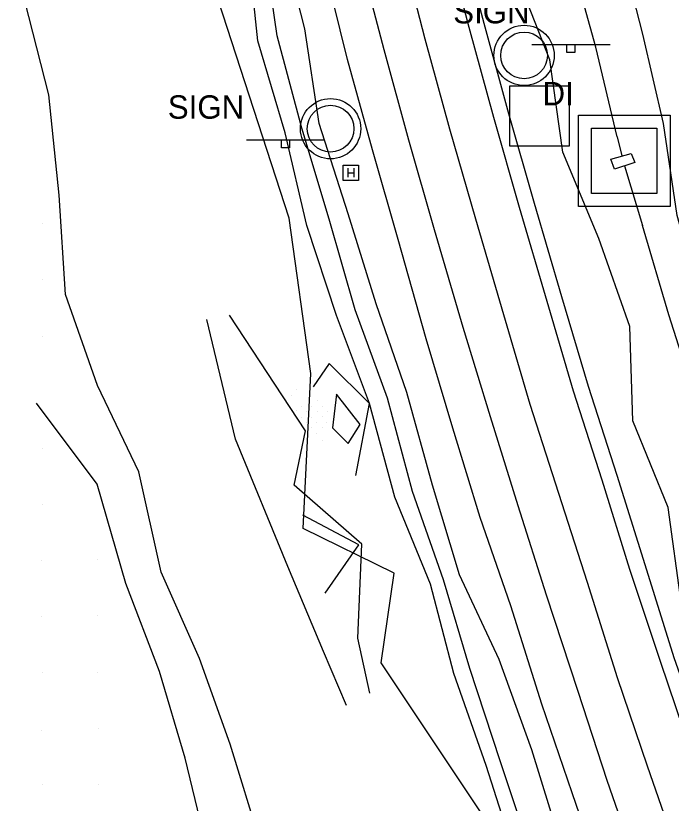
# Model space of a CAD drawing. Extents: x 1602514 to 1609837, y 863887 to 871157.
# Drawn here: x 1604320.5 to 1604495.8, y 868706.1 to 868916.6 of the extents above; entities that cross this region are included whole.
import ezdxf

# ---------------------------------------------------------------- set-up
doc = ezdxf.new("R2010")
doc.units = 0
for name, color, linetype in [('Drainage-Structures', 7, 'Continuous'), ('Lighting_Signals-Equipment', 7, 'Continuous'), ('Roadway-Signs', 7, 'Continuous'), ('Survey-Centerline', 7, 'Continuous'), ('Survey-Drainage structures-concrete', 7, 'Continuous'), ('Survey-Edge of pavement', 7, 'Continuous'), ('Survey-Flow line', 7, 'Continuous'), ('Survey-Ridge Lines', 7, 'Continuous'), ('Survey-Shoulders', 7, 'Continuous'), ('Survey-Signals', 7, 'Continuous'), ('Survey-Spot dirt', 7, 'Continuous'), ('Survey-Spot rock', 7, 'Continuous'), ('Survey-Vegetation trees', 7, 'Continuous'), ('USER-Handhole', 7, 'Continuous')]:
    doc.layers.add(name, color=color, linetype=linetype)

msp = doc.modelspace()

# ---------------------------------------------------------------- linework, layer by layer
at = {"layer": 'Drainage-Structures'}
for p, q in [((1604470.99, 868890.09), (1604495.49, 868890.09)), ((1604470.99, 868865.59), (1604470.99, 868890.09)), ((1604470.99, 868890.09), (1604495.49, 868890.09)), ((1604470.99, 868865.59), (1604470.99, 868890.09)), ((1604495.49, 868890.09), (1604495.49, 868865.59)), ((1604495.49, 868890.09), (1604495.49, 868865.59)), ((1604474.49, 868886.59), (1604491.99, 868886.59)), ((1604474.49, 868869.09), (1604474.49, 868886.59)), ((1604474.49, 868886.59), (1604491.99, 868886.59)), ((1604474.49, 868869.09), (1604474.49, 868886.59)), ((1604491.99, 868886.59), (1604491.99, 868869.09)), ((1604491.99, 868886.59), (1604491.99, 868869.09)), ((1604491.99, 868869.09), (1604474.49, 868869.09)), ((1604491.99, 868869.09), (1604474.49, 868869.09)), ((1604495.49, 868865.59), (1604470.99, 868865.59)), ((1604495.49, 868865.59), (1604470.99, 868865.59))]:
    msp.add_line(p, q, dxfattribs=at)
at = {"layer": 'Lighting_Signals-Equipment'}
msp.add_lwpolyline([(1604452.56, 868881.84), (1604468.56, 868881.84), (1604468.56, 868897.84), (1604452.56, 868897.84)], close=True, dxfattribs=at)
msp.add_lwpolyline([(1604452.56, 868881.84), (1604468.56, 868881.84), (1604468.56, 868897.84), (1604452.56, 868897.84)], close=True, dxfattribs=at)
at = {"layer": 'Roadway-Signs'}
for p, q in [((1604458.57, 868908.94), (1604479.47, 868908.94)), ((1604458.57, 868908.94), (1604479.47, 868908.94)), ((1604467.92, 868906.84), (1604467.92, 868908.94)), ((1604467.92, 868906.84), (1604467.92, 868908.94)), ((1604468.97, 868908.94), (1604468.97, 868908.94)), ((1604468.97, 868908.94), (1604468.97, 868908.94)), ((1604470.02, 868908.94), (1604470.02, 868906.84)), ((1604470.02, 868908.94), (1604470.02, 868906.84)), ((1604470.02, 868906.84), (1604467.92, 868906.84)), ((1604470.02, 868906.84), (1604467.92, 868906.84)), ((1604382.22, 868883.46), (1604403.12, 868883.46)), ((1604382.22, 868883.46), (1604403.12, 868883.46)), ((1604391.57, 868881.36), (1604391.57, 868883.46)), ((1604391.57, 868881.36), (1604391.57, 868883.46)), ((1604392.62, 868883.46), (1604392.62, 868883.46)), ((1604392.62, 868883.46), (1604392.62, 868883.46)), ((1604393.67, 868883.46), (1604393.67, 868881.36)), ((1604393.67, 868883.46), (1604393.67, 868881.36)), ((1604393.67, 868881.36), (1604391.57, 868881.36)), ((1604393.67, 868881.36), (1604391.57, 868881.36))]:
    msp.add_line(p, q, dxfattribs=at)
at = {"layer": 'Survey-Centerline'}
msp.add_lwpolyline([(1604581.44, 868481.09), (1604571.34, 868503.97), (1604561.56, 868526.97), (1604551.97, 868550.06), (1604542.71, 868573.28), (1604533.56, 868596.55), (1604523.63, 868621.98), (1604514.83, 868645.38), (1604506.1, 868668.81), (1604497.66, 868692.34), (1604489.5, 868715.97), (1604481.4, 868739.62), (1604473.39, 868765.08), (1604465.73, 868788.88), (1604458.1, 868812.69), (1604451, 868836.66), (1604443.51, 868862.25), (1604436.63, 868886.29), (1604429.99, 868910.39), (1604423.73, 868934.59)], dxfattribs=at)
msp.add_lwpolyline([(1604581.44, 868481.09), (1604571.34, 868503.97), (1604561.56, 868526.97), (1604551.97, 868550.06), (1604542.71, 868573.28), (1604533.56, 868596.55), (1604523.63, 868621.98), (1604514.83, 868645.38), (1604506.1, 868668.81), (1604497.66, 868692.34), (1604489.5, 868715.97), (1604481.4, 868739.62), (1604473.39, 868765.08), (1604465.73, 868788.88), (1604458.1, 868812.69), (1604451, 868836.66), (1604443.51, 868862.25), (1604436.63, 868886.29), (1604429.99, 868910.39), (1604423.73, 868934.59)], dxfattribs=at)
at = {"layer": 'Survey-Drainage structures-concrete'}
msp.add_lwpolyline([(1604479.68, 868878.3), (1604485.13, 868879.84), (1604486.1, 868877.4), (1604480.62, 868875.64)], close=True, dxfattribs=at)
msp.add_lwpolyline([(1604479.68, 868878.3), (1604485.13, 868879.84), (1604486.1, 868877.4), (1604480.62, 868875.64)], close=True, dxfattribs=at)
at = {"layer": 'Survey-Edge of pavement'}
for points in [[(1604592.91, 868485.86), (1604582.8, 868508.73), (1604573.03, 868531.74), (1604563.26, 868554.75), (1604554, 868577.97), (1604544.85, 868601.23), (1604535.01, 868625.97), (1604526.24, 868649.39), (1604517.66, 868672.87), (1604509.23, 868696.4), (1604501.06, 868720.03), (1604493.04, 868743.71), (1604484.74, 868768.56), (1604477.34, 868792.44), (1604469.71, 868816.25), (1604462.61, 868840.22), (1604455.25, 868865.35), (1604448.37, 868889.39), (1604441.73, 868913.49), (1604435.47, 868937.69)], [(1604592.91, 868485.86), (1604582.8, 868508.73), (1604573.03, 868531.74), (1604563.26, 868554.75), (1604554, 868577.97), (1604544.85, 868601.23), (1604535.01, 868625.97), (1604526.24, 868649.39), (1604517.66, 868672.87), (1604509.23, 868696.4), (1604501.06, 868720.03), (1604493.04, 868743.71), (1604484.74, 868768.56), (1604477.34, 868792.44), (1604469.71, 868816.25), (1604462.61, 868840.22), (1604455.25, 868865.35), (1604448.37, 868889.39), (1604441.73, 868913.49), (1604435.47, 868937.69)], [(1604570.96, 868476.74), (1604560.86, 868499.61), (1604551.08, 868522.62), (1604541.49, 868545.7), (1604532.23, 868568.93), (1604523.08, 868592.19), (1604512.78, 868618.17), (1604503.9, 868641.54), (1604495.32, 868665.02), (1604486.88, 868688.56), (1604478.71, 868712.18), (1604470.88, 868735.92), (1604462.47, 868761.74), (1604454.88, 868785.56), (1604447.48, 868809.43), (1604440.12, 868833.32), (1604432.5, 868859.35), (1604425.62, 868883.39), (1604418.98, 868907.49), (1604412.72, 868931.69)], [(1604570.96, 868476.74), (1604560.86, 868499.61), (1604551.08, 868522.62), (1604541.49, 868545.7), (1604532.23, 868568.93), (1604523.08, 868592.19), (1604512.78, 868618.17), (1604503.9, 868641.54), (1604495.32, 868665.02), (1604486.88, 868688.56), (1604478.71, 868712.18), (1604470.88, 868735.92), (1604462.47, 868761.74), (1604454.88, 868785.56), (1604447.48, 868809.43), (1604440.12, 868833.32), (1604432.5, 868859.35), (1604425.62, 868883.39), (1604418.98, 868907.49), (1604412.72, 868931.69)]]:
    msp.add_lwpolyline(points, dxfattribs=at)
at = {"layer": 'Survey-Flow line'}
for p, q in [((1604481.36, 868884.29), (1604482.63, 868879.14)), ((1604481.36, 868884.29), (1604482.63, 868879.14)), ((1604483.35, 868876.51), (1604488.15, 868860.51)), ((1604483.35, 868876.51), (1604488.15, 868860.51))]:
    msp.add_line(p, q, dxfattribs=at)
for points in [[(1604481.36, 868884.29), (1604475.64, 868908.22), (1604469.14, 868931.65), (1604463.08, 868955.47), (1604458.26, 868979.46), (1604449.71, 869003.69), (1604443.08, 869026.72), (1604439.12, 869050.16), (1604431.9, 869074.97), (1604426.97, 869098.97), (1604423.02, 869123.51), (1604419.66, 869147.75), (1604413.92, 869171.75), (1604412.56, 869196.69), (1604406.79, 869220.46), (1604403.76, 869245.16), (1604400.6, 869269.02), (1604399.12, 869279.06)], [(1604481.36, 868884.29), (1604475.64, 868908.22), (1604469.14, 868931.65), (1604463.08, 868955.47), (1604458.26, 868979.46), (1604449.71, 869003.69), (1604443.08, 869026.72), (1604439.12, 869050.16), (1604431.9, 869074.97), (1604426.97, 869098.97), (1604423.02, 869123.51), (1604419.66, 869147.75), (1604413.92, 869171.75), (1604412.56, 869196.69), (1604406.79, 869220.46), (1604403.76, 869245.16), (1604400.6, 869269.02), (1604399.12, 869279.06)], [(1604537.67, 868479.78), (1604531.49, 868504.94), (1604521.95, 868528.36), (1604512.39, 868552.01), (1604502.89, 868575.32), (1604493.37, 868598.54), (1604484.21, 868622.28), (1604474.86, 868645.6), (1604466.13, 868669.53), (1604457.95, 868693.59), (1604450.01, 868717.41), (1604441.97, 868742.06), (1604434.89, 868765.77), (1604426.64, 868789.43), (1604419.87, 868814.36), (1604411.3, 868838), (1604404.27, 868862.24), (1604397, 868886.54), (1604390.36, 868911.27), (1604386.73, 868936.5)], [(1604537.67, 868479.78), (1604531.49, 868504.94), (1604521.95, 868528.36), (1604512.39, 868552.01), (1604502.89, 868575.32), (1604493.37, 868598.54), (1604484.21, 868622.28), (1604474.86, 868645.6), (1604466.13, 868669.53), (1604457.95, 868693.59), (1604450.01, 868717.41), (1604441.97, 868742.06), (1604434.89, 868765.77), (1604426.64, 868789.43), (1604419.87, 868814.36), (1604411.3, 868838), (1604404.27, 868862.24), (1604397, 868886.54), (1604390.36, 868911.27), (1604386.73, 868936.5)], [(1604631.16, 868467.42), (1604624.49, 868491.01), (1604614.43, 868513.69), (1604605.42, 868536.34), (1604595.9, 868559.08), (1604587.3, 868581.88), (1604579.51, 868605.45), (1604568.58, 868627.9), (1604559.84, 868650.74), (1604547.23, 868672.57), (1604538.84, 868695.58), (1604533.62, 868719.75), (1604526.86, 868743.71), (1604517.89, 868765.93), (1604508.44, 868789.46), (1604502.45, 868813.72), (1604495.18, 868836.65), (1604488.15, 868860.51)], [(1604631.16, 868467.42), (1604624.49, 868491.01), (1604614.43, 868513.69), (1604605.42, 868536.34), (1604595.9, 868559.08), (1604587.3, 868581.88), (1604579.51, 868605.45), (1604568.58, 868627.9), (1604559.84, 868650.74), (1604547.23, 868672.57), (1604538.84, 868695.58), (1604533.62, 868719.75), (1604526.86, 868743.71), (1604517.89, 868765.93), (1604508.44, 868789.46), (1604502.45, 868813.72), (1604495.18, 868836.65), (1604488.15, 868860.51)]]:
    msp.add_lwpolyline(points, dxfattribs=at)
at = {"layer": 'Survey-Ridge Lines'}
msp.add_line((1604415.19, 868735.5), (1604412.02, 868750.19), dxfattribs=at)
msp.add_line((1604415.19, 868735.5), (1604412.02, 868750.19), dxfattribs=at)
for points in [[(1604484.44, 868512.77), (1604471.23, 868535.6), (1604456.61, 868557.12), (1604443.28, 868578.98), (1604434.63, 868603.63), (1604419.68, 868625.03), (1604407.62, 868648.56), (1604398.97, 868673.19), (1604385.98, 868695.5), (1604377.79, 868721.88), (1604369.61, 868744.74), (1604359.38, 868767.89), (1604353.35, 868794.66), (1604342.37, 868817.81), (1604333.79, 868842.09), (1604332.04, 868868.63), (1604329.31, 868895.47), (1604322.89, 868920.63), (1604325.28, 868948.19), (1604325.84, 868972.83), (1604330.44, 869001.73), (1604324.91, 869028.41), (1604328.01, 869053.17), (1604333.56, 869080.61)], [(1604484.44, 868512.77), (1604471.23, 868535.6), (1604456.61, 868557.12), (1604443.28, 868578.98), (1604434.63, 868603.63), (1604419.68, 868625.03), (1604407.62, 868648.56), (1604398.97, 868673.19), (1604385.98, 868695.5), (1604377.79, 868721.88), (1604369.61, 868744.74), (1604359.38, 868767.89), (1604353.35, 868794.66), (1604342.37, 868817.81), (1604333.79, 868842.09), (1604332.04, 868868.63), (1604329.31, 868895.47), (1604322.89, 868920.63), (1604325.28, 868948.19), (1604325.84, 868972.83), (1604330.44, 869001.73), (1604324.91, 869028.41), (1604328.01, 869053.17), (1604333.56, 869080.61)], [(1604525.88, 868529.99), (1604516.28, 868553.56), (1604507.05, 868576.96), (1604497.7, 868600.23), (1604489.01, 868624.08), (1604479.42, 868647.29), (1604473.39, 868672.13), (1604465.92, 868696.34), (1604458.57, 868720.34), (1604449.79, 868744.52), (1604439.2, 868767.16), (1604431.98, 868791.15), (1604425.09, 868815.9), (1604416.9, 868839.64), (1604409.38, 868863.7), (1604401.6, 868887.81), (1604397.76, 868913.18), (1604391.53, 868937.69)], [(1604525.88, 868529.99), (1604516.28, 868553.56), (1604507.05, 868576.96), (1604497.7, 868600.23), (1604489.01, 868624.08), (1604479.42, 868647.29), (1604473.39, 868672.13), (1604465.92, 868696.34), (1604458.57, 868720.34), (1604449.79, 868744.52), (1604439.2, 868767.16), (1604431.98, 868791.15), (1604425.09, 868815.9), (1604416.9, 868839.64), (1604409.38, 868863.7), (1604401.6, 868887.81), (1604397.76, 868913.18), (1604391.53, 868937.69)], [(1604517.46, 868526.49), (1604508.17, 868550.33), (1604497.85, 868573.34), (1604488.7, 868596.71), (1604479.59, 868620.54), (1604470.72, 868644.05), (1604462.42, 868668.2), (1604453.99, 868692.22), (1604446.34, 868716.16), (1604437.68, 868740.71), (1604431.41, 868764.65), (1604421.86, 868787.91), (1604415.12, 868812.95), (1604406.23, 868836.52), (1604398.33, 868860.54), (1604392.52, 868885.3), (1604385.23, 868909.94), (1604382.59, 868935.47)], [(1604517.46, 868526.49), (1604508.17, 868550.33), (1604497.85, 868573.34), (1604488.7, 868596.71), (1604479.59, 868620.54), (1604470.72, 868644.05), (1604462.42, 868668.2), (1604453.99, 868692.22), (1604446.34, 868716.16), (1604437.68, 868740.71), (1604431.41, 868764.65), (1604421.86, 868787.91), (1604415.12, 868812.95), (1604406.23, 868836.52), (1604398.33, 868860.54), (1604392.52, 868885.3), (1604385.23, 868909.94), (1604382.59, 868935.47)], [(1604601.1, 868561.24), (1604594.72, 868584.84), (1604587.27, 868608.51), (1604577.93, 868631.55), (1604568.41, 868653.96), (1604557.83, 868676.52), (1604551.51, 868700.12), (1604544.09, 868723.37), (1604537.6, 868747.39), (1604529.3, 868769.52), (1604521.74, 868793.75), (1604514.12, 868817.46), (1604504.05, 868839.28), (1604497.45, 868863.24), (1604493.73, 868887.83), (1604488.19, 868911.68), (1604482.21, 868935.03)], [(1604601.1, 868561.24), (1604594.72, 868584.84), (1604587.27, 868608.51), (1604577.93, 868631.55), (1604568.41, 868653.96), (1604557.83, 868676.52), (1604551.51, 868700.12), (1604544.09, 868723.37), (1604537.6, 868747.39), (1604529.3, 868769.52), (1604521.74, 868793.75), (1604514.12, 868817.46), (1604504.05, 868839.28), (1604497.45, 868863.24), (1604493.73, 868887.83), (1604488.19, 868911.68), (1604482.21, 868935.03)], [(1604580.26, 868552.59), (1604568.53, 868574.4), (1604563.05, 868598.98), (1604553.96, 868622.19), (1604545.16, 868645.21), (1604532.68, 868667.14), (1604527.97, 868691.68), (1604520.41, 868715.18), (1604510.05, 868737.96), (1604498.44, 868759.81), (1604495.03, 868785.14), (1604485.51, 868808.3), (1604484.73, 868833.56), (1604476.48, 868857.09), (1604466.79, 868880.12), (1604463.34, 868904.83), (1604454.33, 868927.82)], [(1604580.26, 868552.59), (1604568.53, 868574.4), (1604563.05, 868598.98), (1604553.96, 868622.19), (1604545.16, 868645.21), (1604532.68, 868667.14), (1604527.97, 868691.68), (1604520.41, 868715.18), (1604510.05, 868737.96), (1604498.44, 868759.81), (1604495.03, 868785.14), (1604485.51, 868808.3), (1604484.73, 868833.56), (1604476.48, 868857.09), (1604466.79, 868880.12), (1604463.34, 868904.83), (1604454.33, 868927.82)], [(1604394.96, 868791.16), (1604397.98, 868805.61), (1604377.6, 868836.58)], [(1604394.96, 868791.16), (1604397.98, 868805.61), (1604377.6, 868836.58)], [(1604408.97, 868732.19), (1604402.75, 868746.65), (1604393.28, 868769.36), (1604379.22, 868803.41), (1604371.59, 868835.41)], [(1604408.97, 868732.19), (1604402.75, 868746.65), (1604393.28, 868769.36), (1604379.22, 868803.41), (1604371.59, 868835.41)], [(1604411.43, 868793.68), (1604415.12, 868812.95), (1604404.35, 868823.61), (1604400.01, 868817.42)], [(1604411.43, 868793.68), (1604415.12, 868812.95), (1604404.35, 868823.61), (1604400.01, 868817.42)], [(1604473.45, 868508.21), (1604462.16, 868531.98), (1604447.84, 868553.67), (1604427.45, 868572.81), (1604422.01, 868598.88), (1604406.2, 868620.01), (1604394.65, 868643.92), (1604390.97, 868670.42), (1604372.39, 868690.85), (1604365.74, 868718.09), (1604358.94, 868741.3), (1604349.92, 868764.86), (1604342.27, 868791.38), (1604325.98, 868813.02)], [(1604473.45, 868508.21), (1604462.16, 868531.98), (1604447.84, 868553.67), (1604427.45, 868572.81), (1604422.01, 868598.88), (1604406.2, 868620.01), (1604394.65, 868643.92), (1604390.97, 868670.42), (1604372.39, 868690.85), (1604365.74, 868718.09), (1604358.94, 868741.3), (1604349.92, 868764.86), (1604342.27, 868791.38), (1604325.98, 868813.02)], [(1604412.02, 868750.19), (1604413.02, 868775.37), (1604394.96, 868791.16)], [(1604412.02, 868750.19), (1604413.02, 868775.37), (1604394.96, 868791.16)]]:
    msp.add_lwpolyline(points, dxfattribs=at)
at = {"layer": 'Survey-Shoulders'}
for points in [[(1604596.75, 868487.46), (1604586.65, 868510.33), (1604576.88, 868533.34), (1604567.29, 868556.42), (1604558.03, 868579.64), (1604548.88, 868602.91), (1604539.13, 868627.42), (1604530.59, 868650.91), (1604521.52, 868674.22), (1604513.09, 868697.76), (1604504.92, 868721.38), (1604496.64, 868744.97), (1604488.83, 868769.81), (1604481.32, 868793.66), (1604473.69, 868817.47), (1604466.59, 868841.44), (1604459.27, 868866.41), (1604452.4, 868890.45), (1604445.75, 868914.55), (1604439.34, 868938.71)], [(1604596.75, 868487.46), (1604586.65, 868510.33), (1604576.88, 868533.34), (1604567.29, 868556.42), (1604558.03, 868579.64), (1604548.88, 868602.91), (1604539.13, 868627.42), (1604530.59, 868650.91), (1604521.52, 868674.22), (1604513.09, 868697.76), (1604504.92, 868721.38), (1604496.64, 868744.97), (1604488.83, 868769.81), (1604481.32, 868793.66), (1604473.69, 868817.47), (1604466.59, 868841.44), (1604459.27, 868866.41), (1604452.4, 868890.45), (1604445.75, 868914.55), (1604439.34, 868938.71)], [(1604561.8, 868472.94), (1604551.7, 868495.81), (1604541.23, 868518.53), (1604531.93, 868541.73), (1604522.67, 868564.95), (1604513.52, 868588.22), (1604503.01, 868614.74), (1604494.46, 868638.23), (1604485.88, 868661.71), (1604477.45, 868685.24), (1604469.28, 868708.87), (1604461.19, 868732.52), (1604452.91, 868758.81), (1604444.71, 868782.44), (1604437.43, 868806.35), (1604430.22, 868830.29), (1604422.76, 868856.78), (1604415.88, 868880.82), (1604409.24, 868904.92), (1604403.21, 868929.18)], [(1604561.8, 868472.94), (1604551.7, 868495.81), (1604541.23, 868518.53), (1604531.93, 868541.73), (1604522.67, 868564.95), (1604513.52, 868588.22), (1604503.01, 868614.74), (1604494.46, 868638.23), (1604485.88, 868661.71), (1604477.45, 868685.24), (1604469.28, 868708.87), (1604461.19, 868732.52), (1604452.91, 868758.81), (1604444.71, 868782.44), (1604437.43, 868806.35), (1604430.22, 868830.29), (1604422.76, 868856.78), (1604415.88, 868880.82), (1604409.24, 868904.92), (1604403.21, 868929.18)]]:
    msp.add_lwpolyline(points, dxfattribs=at)
at = {"layer": 'Survey-Signals'}
for centre, radius in [((1604456.45, 868906.03), 8.06), ((1604456.45, 868906.03), 8.06), ((1604456.45, 868906.03), 6.25), ((1604456.45, 868906.03), 6.25), ((1604404.68, 868886.44), 8.06), ((1604404.68, 868886.44), 8.06), ((1604404.68, 868886.44), 6.25), ((1604404.68, 868886.44), 6.25)]:
    msp.add_circle(centre, radius, dxfattribs=at)
at = {"layer": 'Survey-Spot dirt'}
for p, q in [((1604327.64, 868861.06), (1604327.64, 868861.06)), ((1604327.64, 868861.06), (1604327.64, 868861.06)), ((1604327.7, 868846.01), (1604327.7, 868846.01)), ((1604327.7, 868846.01), (1604327.7, 868846.01)), ((1604327.64, 868830.98), (1604327.64, 868830.98)), ((1604327.64, 868830.98), (1604327.64, 868830.98)), ((1604395.54, 868816.62), (1604395.54, 868816.62)), ((1604395.54, 868816.62), (1604395.54, 868816.62)), ((1604394.26, 868815.09), (1604394.26, 868815.09)), ((1604394.26, 868815.09), (1604394.26, 868815.09)), ((1604401.1, 868813.64), (1604401.1, 868813.64)), ((1604401.1, 868813.64), (1604401.1, 868813.64)), ((1604395.52, 868811.04), (1604395.52, 868811.04)), ((1604395.52, 868811.04), (1604395.52, 868811.04)), ((1604396.89, 868812.08), (1604396.89, 868812.08)), ((1604396.89, 868812.08), (1604396.89, 868812.08)), ((1604398.26, 868810.79), (1604398.26, 868810.79)), ((1604398.26, 868810.79), (1604398.26, 868810.79)), ((1604399.52, 868812.16), (1604399.52, 868812.16)), ((1604399.52, 868812.16), (1604399.52, 868812.16)), ((1604401.12, 868810.75), (1604401.12, 868810.75)), ((1604401.12, 868810.75), (1604401.12, 868810.75)), ((1604402.47, 868812.21), (1604402.47, 868812.21)), ((1604402.47, 868812.21), (1604402.47, 868812.21)), ((1604403.84, 868810.94), (1604403.84, 868810.94)), ((1604403.84, 868810.94), (1604403.84, 868810.94)), ((1604396.99, 868809.31), (1604396.99, 868809.31)), ((1604396.99, 868809.31), (1604396.99, 868809.31)), ((1604399.67, 868809.2), (1604399.67, 868809.2)), ((1604399.67, 868809.2), (1604399.67, 868809.2)), ((1604402.39, 868809.43), (1604402.39, 868809.43)), ((1604402.39, 868809.43), (1604402.39, 868809.43)), ((1604398.28, 868807.86), (1604398.28, 868807.86)), ((1604398.28, 868807.86), (1604398.28, 868807.86)), ((1604399.63, 868806.48), (1604399.63, 868806.48)), ((1604399.63, 868806.48), (1604399.63, 868806.48)), ((1604401.03, 868807.96), (1604401.03, 868807.96)), ((1604401.03, 868807.96), (1604401.03, 868807.96)), ((1604402.46, 868806.5), (1604402.46, 868806.5)), ((1604402.46, 868806.5), (1604402.46, 868806.5)), ((1604403.59, 868808), (1604403.59, 868808)), ((1604403.59, 868808), (1604403.59, 868808)), ((1604400.99, 868804.85), (1604400.99, 868804.85)), ((1604400.99, 868804.85), (1604400.99, 868804.85)), ((1604402.52, 868803.16), (1604402.52, 868803.16)), ((1604402.52, 868803.16), (1604402.52, 868803.16)), ((1604327.67, 868801.03), (1604327.67, 868801.03)), ((1604327.67, 868801.03), (1604327.67, 868801.03)), ((1604327.49, 868785.96), (1604327.49, 868785.96)), ((1604327.49, 868785.96), (1604327.49, 868785.96)), ((1604327.41, 868771.05), (1604327.41, 868771.05)), ((1604327.41, 868771.05), (1604327.41, 868771.05)), ((1604342.37, 868771.37), (1604342.37, 868771.37)), ((1604342.37, 868771.37), (1604342.37, 868771.37)), ((1604327.47, 868756.01), (1604327.47, 868756.01)), ((1604327.47, 868756.01), (1604327.47, 868756.01)), ((1604342.34, 868756.15), (1604342.34, 868756.15)), ((1604342.34, 868756.15), (1604342.34, 868756.15)), ((1604327.55, 868741.08), (1604327.55, 868741.08)), ((1604327.55, 868741.08), (1604327.55, 868741.08)), ((1604342.36, 868740.95), (1604342.36, 868740.95)), ((1604342.36, 868740.95), (1604342.36, 868740.95)), ((1604342.53, 868725.97), (1604342.53, 868725.97)), ((1604342.53, 868725.97), (1604342.53, 868725.97)), ((1604327.26, 868725.57), (1604327.26, 868725.57)), ((1604327.26, 868725.57), (1604327.26, 868725.57)), ((1604327.54, 868711.09), (1604327.54, 868711.09)), ((1604327.54, 868711.09), (1604327.54, 868711.09)), ((1604342.62, 868711.08), (1604342.62, 868711.08)), ((1604342.62, 868711.08), (1604342.62, 868711.08))]:
    msp.add_line(p, q, dxfattribs=at)
at = {"layer": 'Survey-Spot rock'}
msp.add_lwpolyline([(1604406.28, 868815.43), (1604405.2, 868806.45), (1604409.39, 868802.29), (1604412.57, 868807.31)], close=True, dxfattribs=at)
msp.add_lwpolyline([(1604406.28, 868815.43), (1604405.2, 868806.45), (1604409.39, 868802.29), (1604412.57, 868807.31)], close=True, dxfattribs=at)
msp.add_lwpolyline([(1604403.23, 868762.2), (1604412.26, 868775.14), (1604397.26, 868783.1)], dxfattribs=at)
msp.add_lwpolyline([(1604403.23, 868762.2), (1604412.26, 868775.14), (1604397.26, 868783.1)], dxfattribs=at)
at = {"layer": 'Survey-Vegetation trees'}
msp.add_lwpolyline([(1604524.07, 868408.2), (1604517.77, 868467), (1604534.09, 868482.63), (1604505.47, 868507.06), (1604501.28, 868558.85), (1604491.05, 868596.73), (1604473.3, 868624.95), (1604454.35, 868655.26), (1604446.59, 868701.1), (1604418.23, 868743.65), (1604421.67, 868767.54), (1604397.33, 868779.5), (1604399.43, 868821.02), (1604393.6, 868862.55), (1604374.72, 868920.64), (1604364.46, 868971.73), (1604349.54, 869020.72), (1604352.1, 869071.58), (1604327.15, 869144.6), (1604316.89, 869209.93), (1604321.32, 869253.32)], dxfattribs=at)
msp.add_lwpolyline([(1604524.07, 868408.2), (1604517.77, 868467), (1604534.09, 868482.63), (1604505.47, 868507.06), (1604501.28, 868558.85), (1604491.05, 868596.73), (1604473.3, 868624.95), (1604454.35, 868655.26), (1604446.59, 868701.1), (1604418.23, 868743.65), (1604421.67, 868767.54), (1604397.33, 868779.5), (1604399.43, 868821.02), (1604393.6, 868862.55), (1604374.72, 868920.64), (1604364.46, 868971.73), (1604349.54, 869020.72), (1604352.1, 869071.58), (1604327.15, 869144.6), (1604316.89, 869209.93), (1604321.32, 869253.32)], dxfattribs=at)
at = {"layer": 'USER-Handhole'}
for p, q in [((1604408.03, 868876.68), (1604412.17, 868876.68)), ((1604408.03, 868872.55), (1604408.03, 868876.68)), ((1604408.03, 868876.68), (1604412.17, 868876.68)), ((1604408.03, 868872.55), (1604408.03, 868876.68)), ((1604409.32, 868875.85), (1604409.32, 868873.47)), ((1604409.32, 868875.85), (1604409.32, 868873.47)), ((1604410.88, 868875.85), (1604410.88, 868873.47)), ((1604410.88, 868875.85), (1604410.88, 868873.47)), ((1604412.17, 868876.68), (1604412.17, 868872.55)), ((1604412.17, 868876.68), (1604412.17, 868872.55)), ((1604409.32, 868874.61), (1604410.88, 868874.61)), ((1604409.32, 868874.61), (1604410.88, 868874.61)), ((1604412.17, 868872.55), (1604408.03, 868872.55)), ((1604412.17, 868872.55), (1604408.03, 868872.55))]:
    msp.add_line(p, q, dxfattribs=at)

# ---------------------------------------------------------------- texts
at = {"layer": 'Drainage-Structures'}
msp.add_text('DI', height=6.25, dxfattribs=at).set_placement((1604461.39, 868892.69))
msp.add_text('DI', height=6.25, dxfattribs=at).set_placement((1604461.39, 868892.69))
at = {"layer": 'Roadway-Signs'}
for p in [(1604437.49, 868914.6), (1604437.49, 868914.6), (1604361.14, 868889.11), (1604361.14, 868889.11)]:
    msp.add_text('SIGN', height=6.25, dxfattribs=at).set_placement(p)

doc.saveas('drawing.dxf')
